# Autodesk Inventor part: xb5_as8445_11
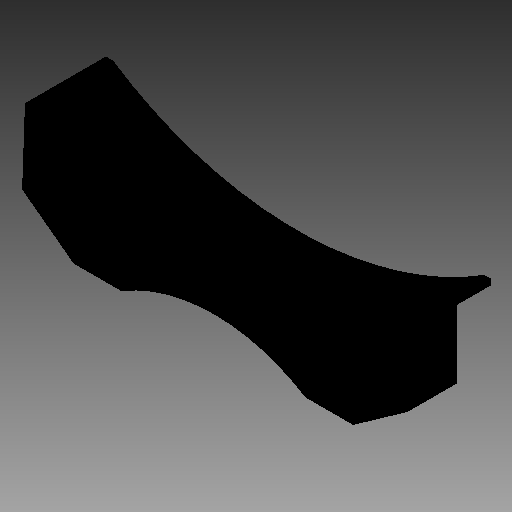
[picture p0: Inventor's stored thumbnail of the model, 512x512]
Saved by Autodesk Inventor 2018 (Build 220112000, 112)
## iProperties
Company: TraceParts S.A.
Created: 2018-04
Part Number: xb5_as8445_11
Checked By: TraceParts S.A.
Material: Generic
Catalog Web Link: www.traceparts.com
Document SubType Name: Modeling
Designer: TraceParts
Density: 1 g/cm^3
Appearance: Default
Author: TraceParts
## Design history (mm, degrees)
feature "xb5_as8445_11.ipt"
body "Solid1"
